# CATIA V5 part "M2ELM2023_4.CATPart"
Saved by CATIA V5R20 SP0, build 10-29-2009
Part number: M2ELM2022
Bounding box of the stored display mesh (mm): x -174.303 to 174.354, y -100 to 73, z -174.305 to 174.305
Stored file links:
  E:\0 Pedagogie\01 Hamma Lakhdar University\0Pedagogie\2023 2024\M2ELM CFAO\Travail a domicile 3\M2ELM2024_4.CATPart
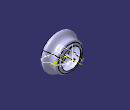
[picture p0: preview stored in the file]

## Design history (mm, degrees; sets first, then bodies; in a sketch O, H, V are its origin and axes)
Body1 (main body)
  Sketch1 on xy-plane, origin (0, 0, 0), H (1, 0, 0), V (0, 1, 0)
    line L1 (11, 73) -> (62, 73)
    arc A1 centre (62, 34.8696) radius 38.1304 from (62, 73) to (97, 50) cw
    line L2 (97, 50) -> (122, 40)
    point P4 (122, 40)
    spline S1 through (122, 40) (138, 29) (138, 12) (169, -51) (151, -100)
    point P5 (11, -90)
    line L3 (11, 73) -> (11, -90)
    axis line L4 (0, 81.8157) -> (0, -112.7382)
    point P6 (0, 81.8157)
    line L5 (151, -100) -> (110, -100)
    line L6 (110, -100) -> (90, -90)
    line L7 (90, -90) -> (11, -90)
    point P10 (11, -90)
    point P11 (151, -100)
    point P12 (122, 40)
    point P13 (151, -100)
    length L1 = 51
    length L3 = 163
    length L7 = 79
    horizontal: L1 H, L5 H, L7 H
    tangency: A1 L1
    coincidence: P12 P4, P6 V, P10 L3, P13 P11, P5 P10
    vertical: L3 V, L4 V
  Shaft1: profile Sketch1, axis Sketch1.L4, angle 360
  Shell1: IntOffset 2, Face face of Shaft1 from Sketch1.L1, ExtOffset 0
